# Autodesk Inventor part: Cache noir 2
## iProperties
Shininess: 20.0
Angle Display Precision: 2
Document Length Units: 11269
Document Angle Units: 11279
Document Time Units: 11290
Document Mass Units: 11283
Document Length Units Precision: 3
Document Angle Units Precision: 2
Created: 2002-09
Part Number: Cache noir 2
Material: Par défaut
Document SubType Name: Modélisation
Designer: administrateur
Density: 0.0
Volumn: 0.0
Area: 0.0
PropertySet Name: Model Information
Control State: 0
Master: False
Checked Out: False
Author: administrateur
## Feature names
1. Extrusion1
2. Extrusion2
3. Extrusion3
4. Extrusion4
5. Congé1 [Fillet]
6. Congé2 [Fillet]
7. Congé3 [Fillet]
